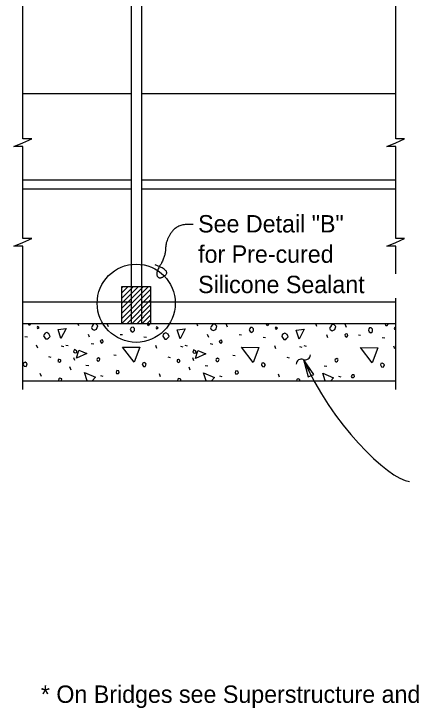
# Model space of a CAD drawing. Extents: x 120631.6 to 120706.2, y 120663.5 to 120716.4.
# Drawn here: x 120634.37 to 120638.99, y 120690.08 to 120698.14 of the extents above; entities that cross this region are included whole.
import ezdxf

# ---------------------------------------------------------------- set-up
doc = ezdxf.new("R2010")
doc.units = 0
for name, color, linetype in [('Dimension', 7, 'Continuous'), ('Miscellaneous', 7, 'Continuous'), ('Patterning', 7, 'Continuous'), ('TrafBarrierConc', 7, 'Continuous')]:
    doc.layers.add(name, color=color, linetype=linetype)

msp = doc.modelspace()

# ---------------------------------------------------------------- linework, layer by layer
at = {"layer": 'Dimension'}
for points in [[(120634.4764, 120697.2127), (120634.4764, 120699.4757), (120634.373, 120699.4757), (120634.4764, 120699.5207), (120634.5797, 120699.5657), (120634.4764, 120699.5657), (120634.4764, 120702.646)], [(120638.8057, 120697.2127), (120638.8057, 120699.4757), (120638.7024, 120699.4757), (120638.8057, 120699.5207), (120638.909, 120699.5657), (120638.8057, 120699.5657), (120638.8057, 120702.646)], [(120634.4764, 120696.2127), (120634.4764, 120696.597), (120634.373, 120696.597), (120634.4764, 120696.642), (120634.5797, 120696.687), (120634.4764, 120696.687), (120634.4764, 120697.2127)], [(120638.8057, 120696.2127), (120638.8057, 120696.597), (120638.7024, 120696.597), (120638.8057, 120696.642), (120638.909, 120696.687), (120638.8057, 120696.687), (120638.8057, 120697.2127)], [(120634.4764, 120693.7786), (120634.4764, 120695.4418), (120634.373, 120695.4418), (120634.4764, 120695.4868), (120634.5797, 120695.5318), (120634.4764, 120695.5318), (120634.4764, 120696.2127)], [(120638.8057, 120695.1212), (120638.8057, 120695.4418), (120638.7024, 120695.4418), (120638.8057, 120695.4868), (120638.909, 120695.5318), (120638.8057, 120695.5318), (120638.8057, 120696.2127)], [(120638.8057, 120693.7786), (120638.8057, 120694.838)]]:
    msp.add_lwpolyline(points, dxfattribs=at)
msp.add_lwpolyline([(120637.7342, 120694.1286), (120637.7911, 120693.9252), (120637.855, 120693.9553)], close=True, dxfattribs=at)
msp.add_circle((120635.794, 120694.7801), 0.4535, dxfattribs=at)
for centre, start, end in [((120637.7564, 120694.1833), 247.50791, 359.23513), ((120637.7108, 120694.0731), 67.50791, 179.23513)]:
    msp.add_arc(centre, 0.0596, start, end, dxfattribs=at)
for points, degree in [([(120636.4538, 120695.6922), (120636.2854, 120695.7125), (120636.1346, 120695.5117), (120636.1346, 120695.3251), (120636.0119, 120695.1238), (120636.0708, 120695.0551), (120636.1936, 120695.1582), (120636.0119, 120695.2269)], 2), ([(120637.7342, 120694.1286), (120638.0484, 120693.4002), (120638.7122, 120692.7395), (120638.9679, 120692.7128)], 3)]:
    msp.add_open_spline(points, degree=degree, dxfattribs=at)
at = {"layer": 'Miscellaneous'}
for p, q in [((120635.1268, 120694.5182), (120635.1157, 120694.546)), ((120635.4698, 120694.5075), (120635.4556, 120694.5429)), ((120636.5092, 120694.5146), (120636.4967, 120694.546)), ((120636.8522, 120694.5041), (120636.838, 120694.5394)), ((120637.8916, 120694.5111), (120637.8777, 120694.546)), ((120638.2346, 120694.5005), (120638.2204, 120694.5359)), ((120634.501, 120694.3944), (120634.5311, 120694.3891)), ((120635.2523, 120694.3856), (120635.2399, 120694.4192)), ((120635.6077, 120694.4192), (120635.6324, 120694.4157)), ((120636.6347, 120694.3821), (120636.6223, 120694.4157)), ((120636.9901, 120694.4157), (120637.0148, 120694.4121)), ((120638.0171, 120694.3785), (120638.0047, 120694.4121)), ((120638.3724, 120694.4121), (120638.3972, 120694.4086)), ((120635.27, 120694.3149), (120635.3001, 120694.3096)), ((120635.8834, 120694.3909), (120635.9135, 120694.3856)), ((120637.2658, 120694.3873), (120637.2959, 120694.3821)), ((120638.6482, 120694.3838), (120638.6783, 120694.3785)), ((120634.6495, 120694.2601), (120634.6371, 120694.2937)), ((120634.9235, 120694.2866), (120634.9518, 120694.2795)), ((120634.9748, 120694.2955), (120635.0031, 120694.2884)), ((120636.0319, 120694.2566), (120636.0195, 120694.2901)), ((120636.3059, 120694.2831), (120636.3342, 120694.276)), ((120636.3572, 120694.2919), (120636.3855, 120694.2848)), ((120636.6524, 120694.3113), (120636.6824, 120694.306)), ((120637.4143, 120694.253), (120637.4019, 120694.2866)), ((120637.6883, 120694.2795), (120637.7166, 120694.2724)), ((120637.7396, 120694.2884), (120637.7679, 120694.2813)), ((120638.7967, 120694.2495), (120638.7843, 120694.2831)), ((120634.7768, 120694.1611), (120634.8033, 120694.1558)), ((120635.5334, 120694.1823), (120635.5599, 120694.177)), ((120636.1592, 120694.1575), (120636.1857, 120694.1522)), ((120636.9158, 120694.1787), (120636.9423, 120694.1735)), ((120637.5416, 120694.154), (120637.5681, 120694.1487)), ((120635.0809, 120694.1151), (120635.0685, 120694.1487)), ((120636.4633, 120694.1116), (120636.4509, 120694.1452)), ((120635.0384, 120694.0055), (120635.0243, 120694.0409)), ((120635.2099, 120694.0603), (120635.2417, 120694.0568)), ((120636.4208, 120694.002), (120636.4067, 120694.0373)), ((120636.5923, 120694.0568), (120636.6241, 120694.0533)), ((120637.8032, 120693.9984), (120637.7891, 120694.0338)), ((120637.9747, 120694.0533), (120638.0065, 120694.0497)), ((120634.6938, 120693.9295), (120634.6796, 120693.9649)), ((120635.3779, 120693.9419), (120635.4061, 120693.9348)), ((120636.0761, 120693.926), (120636.062, 120693.9613)), ((120636.7603, 120693.9383), (120636.7885, 120693.9313)), ((120637.4585, 120693.9224), (120637.4444, 120693.9578)), ((120638.1427, 120693.9348), (120638.1709, 120693.9277))]:
    msp.add_line(p, q, dxfattribs=at)
for points in [[(120634.5488, 120694.5235), (120634.5414, 120694.546)], [(120634.5679, 120694.546), (120634.5488, 120694.5235)], [(120634.6478, 120694.4881), (120634.6672, 120694.497), (120634.6602, 120694.5041), (120634.6478, 120694.5093), (120634.6424, 120694.497), (120634.6478, 120694.4881)], [(120634.92, 120694.3714), (120634.8864, 120694.4758), (120634.9801, 120694.4881), (120634.92, 120694.3714)], [(120635.2806, 120694.481), (120635.3036, 120694.4687), (120635.3336, 120694.481), (120635.346, 120694.5182), (120635.3283, 120694.5359), (120635.3054, 120694.5411), (120635.2948, 120694.5341), (120635.2824, 120694.5146), (120635.2735, 120694.4987), (120635.2806, 120694.481)], [(120635.7243, 120694.4758), (120635.7349, 120694.4545), (120635.7526, 120694.4439), (120635.7668, 120694.4545), (120635.7739, 120694.4651), (120635.7739, 120694.4863), (120635.7579, 120694.5023), (120635.7385, 120694.5005), (120635.7296, 120694.4917), (120635.7243, 120694.4758)], [(120635.9311, 120694.5199), (120635.9227, 120694.546)], [(120635.9532, 120694.546), (120635.9311, 120694.5199)], [(120636.0302, 120694.4846), (120636.0496, 120694.4934), (120636.0426, 120694.5005), (120636.0302, 120694.5058), (120636.0248, 120694.4934), (120636.0302, 120694.4846)], [(120636.3024, 120694.3679), (120636.2688, 120694.4722), (120636.3625, 120694.4846), (120636.3024, 120694.3679)], [(120636.663, 120694.4775), (120636.686, 120694.4651), (120636.716, 120694.4775), (120636.7284, 120694.5146), (120636.7107, 120694.5323), (120636.6878, 120694.5376), (120636.6772, 120694.5306), (120636.6648, 120694.5111), (120636.6559, 120694.4952), (120636.663, 120694.4775)], [(120637.1067, 120694.4722), (120637.1173, 120694.451), (120637.135, 120694.4404), (120637.1492, 120694.451), (120637.1562, 120694.4616), (120637.1562, 120694.4828), (120637.1403, 120694.4987), (120637.1209, 120694.497), (120637.112, 120694.4881), (120637.1067, 120694.4722)], [(120637.3135, 120694.5164), (120637.3039, 120694.546)], [(120637.3386, 120694.546), (120637.3135, 120694.5164)], [(120637.4126, 120694.481), (120637.432, 120694.4899), (120637.4249, 120694.497), (120637.4126, 120694.5023), (120637.4072, 120694.4899), (120637.4126, 120694.481)], [(120637.6848, 120694.3644), (120637.6512, 120694.4687), (120637.7449, 120694.481), (120637.6848, 120694.3644)], [(120638.0454, 120694.474), (120638.0684, 120694.4616), (120638.0984, 120694.474), (120638.1108, 120694.5111), (120638.0931, 120694.5288), (120638.0702, 120694.5341), (120638.0595, 120694.527), (120638.0472, 120694.5075), (120638.0383, 120694.4917), (120638.0454, 120694.474)], [(120638.4891, 120694.4687), (120638.4997, 120694.4474), (120638.5174, 120694.4369), (120638.5316, 120694.4474), (120638.5386, 120694.4581), (120638.5386, 120694.4793), (120638.5227, 120694.4952), (120638.5033, 120694.4934), (120638.4944, 120694.4846), (120638.4891, 120694.4687)], [(120638.6959, 120694.5129), (120638.6852, 120694.546)], [(120638.724, 120694.546), (120638.6959, 120694.5129)], [(120638.8057, 120694.4941), (120638.7949, 120694.4987), (120638.7896, 120694.4863), (120638.7949, 120694.4775)], [(120638.7949, 120694.4775), (120638.8057, 120694.4824)], [(120634.7185, 120694.4033), (120634.7415, 120694.3661), (120634.7644, 120694.3679), (120634.7733, 120694.3768), (120634.7927, 120694.3962), (120634.7804, 120694.4262), (120634.7556, 120694.4404), (120634.7379, 120694.4333), (120634.7238, 120694.4192), (120634.7185, 120694.4033)], [(120636.1009, 120694.3997), (120636.1239, 120694.3626), (120636.1468, 120694.3644), (120636.1557, 120694.3732), (120636.1751, 120694.3926), (120636.1628, 120694.4227), (120636.138, 120694.4369), (120636.1203, 120694.4298), (120636.1062, 120694.4157), (120636.1009, 120694.3997)], [(120637.4833, 120694.3962), (120637.5063, 120694.3591), (120637.5292, 120694.3608), (120637.5381, 120694.3697), (120637.5575, 120694.3891), (120637.5452, 120694.4192), (120637.5204, 120694.4333), (120637.5027, 120694.4262), (120637.4886, 120694.4121), (120637.4833, 120694.3962)], [(120638.221, 120694.3977), (120638.2316, 120694.3871), (120638.2422, 120694.3942), (120638.2493, 120694.4048), (120638.2457, 120694.4225), (120638.2369, 120694.4243), (120638.2245, 120694.4225), (120638.2139, 120694.4119), (120638.221, 120694.3977)], [(120635.3814, 120694.3272), (120635.392, 120694.3167), (120635.4026, 120694.3237), (120635.4097, 120694.3343), (120635.4061, 120694.352), (120635.3973, 120694.3538), (120635.3849, 120694.352), (120635.3743, 120694.3414), (120635.3814, 120694.3272)], [(120636.7638, 120694.3237), (120636.7744, 120694.3131), (120636.785, 120694.3202), (120636.7921, 120694.3308), (120636.7885, 120694.3485), (120636.7797, 120694.3502), (120636.7673, 120694.3485), (120636.7567, 120694.3379), (120636.7638, 120694.3237)], [(120635.0773, 120694.207), (120635.0897, 120694.2053), (120635.1021, 120694.2106), (120635.1056, 120694.2212), (120635.1003, 120694.23), (120635.0897, 120694.2371), (120635.0773, 120694.2424), (120635.0703, 120694.2283), (120635.0667, 120694.2176), (120635.0773, 120694.207)], [(120635.0985, 120694.1434), (120635.1268, 120694.2354), (120635.2205, 120694.1982), (120635.0985, 120694.1434)], [(120635.7685, 120694.0957), (120635.6342, 120694.2724), (120635.834, 120694.2707), (120635.7685, 120694.0957)], [(120636.4597, 120694.2035), (120636.4721, 120694.2018), (120636.4845, 120694.207), (120636.488, 120694.2176), (120636.4827, 120694.2265), (120636.4721, 120694.2336), (120636.4597, 120694.2388), (120636.4527, 120694.2247), (120636.4491, 120694.2141), (120636.4597, 120694.2035)], [(120636.4809, 120694.1399), (120636.5092, 120694.2318), (120636.6029, 120694.1947), (120636.4809, 120694.1399)], [(120637.1509, 120694.0921), (120637.0166, 120694.2689), (120637.2164, 120694.2671), (120637.1509, 120694.0921)], [(120638.5333, 120694.0886), (120638.399, 120694.2654), (120638.5988, 120694.2636), (120638.5333, 120694.0886)], [(120634.4852, 120694.0674), (120634.494, 120694.0515), (120634.5152, 120694.048), (120634.524, 120694.0638), (120634.5276, 120694.078), (120634.5187, 120694.0868), (120634.5028, 120694.0957), (120634.4869, 120694.0904), (120634.4816, 120694.0745), (120634.4852, 120694.0674)], [(120634.8846, 120694.1027), (120634.9041, 120694.0974), (120634.9165, 120694.1063), (120634.9182, 120694.1186), (120634.9147, 120694.1222), (120634.9006, 120694.1293), (120634.8882, 120694.1275), (120634.8864, 120694.1151), (120634.8846, 120694.1027)], [(120635.346, 120694.1081), (120635.3531, 120694.1081), (120635.3672, 120694.1151), (120635.3726, 120694.131), (120635.3708, 120694.1399), (120635.3567, 120694.1469), (120635.339, 120694.1363), (120635.3354, 120694.1257), (120635.339, 120694.1151), (120635.346, 120694.1081)], [(120635.8675, 120694.0638), (120635.8764, 120694.048), (120635.8976, 120694.0444), (120635.9064, 120694.0603), (120635.9099, 120694.0745), (120635.9011, 120694.0833), (120635.8852, 120694.0921), (120635.8693, 120694.0868), (120635.864, 120694.0709), (120635.8675, 120694.0638)], [(120636.267, 120694.0992), (120636.2865, 120694.0939), (120636.2989, 120694.1027), (120636.3006, 120694.1151), (120636.2971, 120694.1186), (120636.283, 120694.1257), (120636.2706, 120694.1239), (120636.2688, 120694.1116), (120636.267, 120694.0992)], [(120636.7284, 120694.1045), (120636.7355, 120694.1045), (120636.7496, 120694.1116), (120636.7549, 120694.1275), (120636.7532, 120694.1363), (120636.739, 120694.1434), (120636.7214, 120694.1328), (120636.7178, 120694.1222), (120636.7214, 120694.1116), (120636.7284, 120694.1045)], [(120637.2499, 120694.0603), (120637.2588, 120694.0444), (120637.2799, 120694.0409), (120637.2888, 120694.0568), (120637.2923, 120694.0709), (120637.2835, 120694.0798), (120637.2676, 120694.0886), (120637.2517, 120694.0833), (120637.2464, 120694.0674), (120637.2499, 120694.0603)], [(120638.1108, 120694.101), (120638.1179, 120694.101), (120638.132, 120694.1081), (120638.1373, 120694.1239), (120638.1356, 120694.1328), (120638.1214, 120694.1399), (120638.1038, 120694.1293), (120638.1002, 120694.1186), (120638.1038, 120694.1081), (120638.1108, 120694.101)], [(120638.6323, 120694.0568), (120638.6411, 120694.0409), (120638.6623, 120694.0373), (120638.6712, 120694.0533), (120638.6747, 120694.0674), (120638.6659, 120694.0762), (120638.65, 120694.0851), (120638.6341, 120694.0798), (120638.6288, 120694.0638), (120638.6323, 120694.0568)], [(120635.5653, 120693.9666), (120635.5865, 120693.9666), (120635.597, 120693.9772), (120635.5918, 120693.9967), (120635.5688, 120693.9984), (120635.5653, 120693.9879), (120635.5599, 120693.979), (120635.5653, 120693.9666), (120635.5617, 120693.9701)], [(120636.9477, 120693.9631), (120636.9689, 120693.9631), (120636.9794, 120693.9737), (120636.9742, 120693.9932), (120636.9511, 120693.9949), (120636.9477, 120693.9843), (120636.9423, 120693.9755), (120636.9477, 120693.9631), (120636.9441, 120693.9666)], [(120634.9241, 120693.8794), (120634.9271, 120693.8835), (120634.9289, 120693.903), (120634.9165, 120693.9083), (120634.9076, 120693.91), (120634.897, 120693.9065), (120634.8935, 120693.903), (120634.8899, 120693.8853)], [(120635.2258, 120693.8794), (120635.194, 120693.9772), (120635.3195, 120693.9224), (120635.2831, 120693.8794)], [(120636.6071, 120693.8794), (120636.5764, 120693.9737), (120636.7019, 120693.9189), (120636.6685, 120693.8794)], [(120637.9883, 120693.8794), (120637.9588, 120693.9701), (120638.0843, 120693.9154), (120638.0539, 120693.8794)], [(120638.2955, 120693.9189), (120638.3167, 120693.9189), (120638.3273, 120693.9295), (120638.322, 120693.949), (120638.299, 120693.9508), (120638.2955, 120693.9401), (120638.2902, 120693.9313), (120638.2955, 120693.9189), (120638.292, 120693.9225)], [(120634.8899, 120693.8853), (120634.8933, 120693.8794)], [(120636.309, 120693.8794), (120636.3095, 120693.88), (120636.3112, 120693.8995), (120636.2989, 120693.9048), (120636.29, 120693.9065), (120636.2794, 120693.903), (120636.2759, 120693.8995), (120636.2723, 120693.8818)], [(120636.2723, 120693.8818), (120636.2737, 120693.8794)], [(120637.6921, 120693.8794), (120637.6936, 120693.8959), (120637.6813, 120693.9012), (120637.6724, 120693.903), (120637.6618, 120693.8995), (120637.6583, 120693.8959), (120637.6549, 120693.8794)]]:
    msp.add_lwpolyline(points, dxfattribs=at)
at = {"layer": 'Patterning'}
for p, q in [((120635.6276, 120694.6639), (120635.9368, 120694.9731)), ((120635.6276, 120694.7228), (120635.8779, 120694.9731)), ((120635.6276, 120694.7817), (120635.819, 120694.9731)), ((120635.6276, 120694.8407), (120635.7601, 120694.9731)), ((120635.6276, 120694.8996), (120635.7011, 120694.9731)), ((120635.6276, 120694.9585), (120635.6422, 120694.9731)), ((120635.6276, 120694.605), (120635.9609, 120694.9383)), ((120635.6276, 120694.546), (120635.9609, 120694.8794)), ((120635.6865, 120694.546), (120635.9609, 120694.8204)), ((120635.7455, 120694.546), (120635.9609, 120694.7615)), ((120635.8044, 120694.546), (120635.9609, 120694.7026)), ((120635.8633, 120694.546), (120635.9609, 120694.6437)), ((120635.9222, 120694.546), (120635.9609, 120694.5847))]:
    msp.add_line(p, q, dxfattribs=at)
msp.add_lwpolyline([(120635.6276, 120694.546), (120635.6276, 120694.9731), (120635.9609, 120694.9731), (120635.9609, 120694.546)], dxfattribs=at)
at = {"layer": 'TrafBarrierConc'}
for p, q in [((120635.733, 120702.4835), (120635.733, 120694.546)), ((120635.8555, 120702.4835), (120635.8555, 120694.546)), ((120634.4764, 120697.2127), (120635.733, 120697.2127)), ((120635.8555, 120697.2127), (120638.8057, 120697.2127)), ((120634.4764, 120696.2127), (120635.733, 120696.2127)), ((120635.8555, 120696.2127), (120638.8057, 120696.2127)), ((120634.4764, 120696.1085), (120635.733, 120696.1085)), ((120635.8555, 120696.1085), (120638.8057, 120696.1085)), ((120634.4764, 120694.796), (120635.733, 120694.796)), ((120635.8555, 120694.796), (120638.8057, 120694.796)), ((120634.4764, 120694.546), (120638.8057, 120694.546)), ((120634.4764, 120693.8794), (120638.8057, 120693.8794))]:
    msp.add_line(p, q, dxfattribs=at)

# ---------------------------------------------------------------- texts
at = {"layer": 'Dimension'}
for s, height, p in [('See Detail "B"', 0.2016, (120636.5123, 120695.6015)), ('for Pre-cured', 0.2016, (120636.5123, 120695.2495)), ('Silicone Sealant', 0.2016, (120636.5123, 120694.8975)), ('* On Bridges see Superstructure and Approach Slab Sheets for actual dimensions and joint orientation. Open ', 0.2016004, (120634.6865, 120690.1437))]:
    msp.add_text(s, height=height, dxfattribs=at).set_placement(p)

doc.saveas('drawing.dxf')
